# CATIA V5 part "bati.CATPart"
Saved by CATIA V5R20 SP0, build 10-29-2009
Part number: bati
Bounding box of the stored display mesh (mm): x -76 to 40, y -41 to 202.5, z -35 to 30
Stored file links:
  F:\Catia_finish\bati.CATPart
  F:\CATIA\Tige.CATPart
  F:\Catia_finish\ASS_compresseur.CATProduct
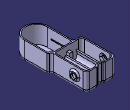
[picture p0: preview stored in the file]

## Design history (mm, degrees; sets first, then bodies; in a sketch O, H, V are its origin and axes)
Parameters
  LENGTH = 20 mm
  LENGTH = 15 mm
  LENGTH = 35 mm
External parameters (linked from other documents)
  External.rayon_piston = 20 mm
  External.excentricite_vilebrequin = 6 mm
  External.longueur_bielle = 35 mm
Set1
  Plane1: linked copy from another document
  Line1: linked copy from another document
  Point1: linked copy from another document
  Line2: linked copy from another document
  Sketch1 on face of Pad2 from Sketch3.L23, origin (-38, 0, 0), H (0, 1, 0), V (0, 0, 1)
    line L1 (59, -2) -> (14, -2)
    line L2 (14, -2) -> (14, 2)
    line L3 (14, 2) -> (59, 2)
    line L4 (59, 2) -> (59, -2)
    reference projected point E1 (55, 0) from Point1
    reference projected line E2 (55, 0) -> (10, 0) from Line2
    length L3 = 45
    distance L4 E1 = 4
    length L2 = 4
    distance L3 E2 = 2
    horizontal: L1 H, L3 H
    vertical: L2 V, L4 V
  Point2: linked copy from another document
  Line3: linked copy from another document
Body1 (main body)
  Sketch2 on xy-plane, origin (0, 0, 0), H (1, 0, 0), V (0, 1, 0)
    point P1 (40, 0)
    line L1 (40, 0) -> (40, 81)
    line L2 (40, 81) -> (30, 81)
    line L3 (30, 81) -> (30, 202.5)
    line L4 (30, 202.5) -> (-10, 202.5)
    line L5 (-10, 202.5) -> (-10, 197.5)
    line L6 (-10, 197.5) -> (-30, 197.5)
    line L7 (-30, 197.5) -> (-30, 202.5)
    point P8 (-30, 202.5)
    line L8 (-30, 202.5) -> (-70, 202.5)
    line L9 (-70, 202.5) -> (-70, 85)
    line L10 (-70, 85) -> (-42, 85)
    line L11 (-42, 85) -> (-42, 0)
    construction line L12 (40, 0) -> (98, 0)
    construction line L13 (-42, 0) -> (-95, 0)
    reference projected line E1 (-20, 120) -> (-20, 20)
    arc A1 centre (-1, 0) radius 41 from (-42, 0) to (40, 0) ccw
    circle A2 centre (0, 0) radius 10
    point P16 (0, 0)
    reference projected point E2 (0, 0)
    axis line L14 (25, 81) -> (-29, 81)
    point P17 (25, 81)
    length L1 = 81 {= External.excentricite_vilebrequin +External.longueur_bielle +40mm}
    distance L9 E1 = 50 {= Sketch2.length(L8) +10mm}
    length L8 = 40 {= LENGTH +20mm}
    length L4 = 40 {= LENGTH +20mm}
    length L6 = 20
    length L3 = 121.5 {= Sketch2.length(L1) *1.5}
    distance L6 L4 = 5
    length L10 = 28
    length L2 = 10
    radius A2 = 10
    coincidence: P1 H, P8 L4, L13 L12, E2 P16, P17 L2
    vertical: L1 V, L3 V, L5 V, L7 V, L9 V, L11 V
    horizontal: L2 H, L4 H, L6 H, L8 H, L10 H, L12 H, L13 H, L14 H
    tangency: A1 L1
  Pad1: profile Sketch2, direction (0, 0, 1), length -30 {= -External.rayon_piston -10mm}, opposite side length 35 {= External.rayon_piston+15mm}
  Sketch3 on end face of Pad1, origin (0, 0, -30), H (1, 0, 0), V (0, 1, 0)
    line L1 (-66, 198.5) -> (-66, 89)
    line L2 (-66, 198.5) -> (-34, 198.5)
    line L3 (-34, 198.5) -> (-34, 193.5)
    line L4 (-34, 193.5) -> (-6, 193.5)
    line L5 (-6, 193.5) -> (-6, 198.5)
    point P7 (-6, 198.5)
    line L6 (-6, 198.5) -> (26, 198.5)
    line L7 (26, 77) -> (36, 77)
    line L8 (36, 77) -> (36, 0)
    point P11 (36, 0)
    reference projected line E1 (-70, 170) -> (-70, 85) from edge [face of Pad1 from Sketch2.L9 | end face of Pad1]
    reference projected line E2 (-30, 202.5) -> (-70, 202.5) from edge [face of Pad1 from Sketch2.L8 | end face of Pad1]
    reference projected line E3 (40, 81) -> (30, 81) from edge [face of Pad1 from Sketch2.L2 | end face of Pad1]
    reference projected line E4 (-30, 165) -> (-30, 170) from edge [face of Pad1 from Sketch2.L7 | end face of Pad1]
    reference projected line E5 (-10, 197.5) -> (-30, 197.5) from edge [face of Pad1 from Sketch2.L6 | end face of Pad1]
    reference projected line E6 (-10, 170) -> (-10, 165) from edge [face of Pad1 from Sketch2.L5 | end face of Pad1]
    construction line L9 (-38, 0) -> (107, 0)
    reference projected point E7 (40, 0) from vertex [face of Pad1 from Sketch2.A1 | end face of Pad1 | face of Pad1 from Sketch2.L1]
    reference projected line E8 (40, 0) -> (40, 85) from edge [face of Pad1 from Sketch2.L1 | end face of Pad1]
    arc A1 centre (-1, 0) radius 37 from (36, 0) to (-38, 0) cw
    point P14 (40, 0)
    line L10 (40, 0) -> (40, 81)
    line L11 (40, 81) -> (30, 81)
    line L12 (30, 81) -> (30, 202.5)
    line L13 (-70, 202.5) -> (-70, 85)
    line L14 (-70, 85) -> (-42, 85)
    line L15 (-42, 85) -> (-42, 0)
    point P21 (-42, 0)
    reference projected line E9 (40, 0) -> (40, 85) from edge [face of Pad1 from Sketch2.L1 | end face of Pad1]
    reference projected line E10 (30, 85) -> (30, 170) from edge [face of Pad1 from Sketch2.L3 | end face of Pad1]
    reference projected line E11 (-70, 170) -> (-70, 85) from edge [face of Pad1 from Sketch2.L9 | end face of Pad1]
    reference projected line E12 (-70, 85) -> (-42, 85) from edge [face of Pad1 from Sketch2.L10 | end face of Pad1]
    reference projected line E13 (-42, 85) -> (-42, 0) from edge [face of Pad1 from Sketch2.L11 | end face of Pad1]
    reference projected line E14 (40, 81) -> (30, 81) from edge [face of Pad1 from Sketch2.L2 | end face of Pad1]
    line L16 (30, 202.5) -> (-10, 202.5)
    line L17 (-10, 202.5) -> (-10, 197.5)
    line L18 (-10, 197.5) -> (-30, 197.5)
    line L19 (-30, 197.5) -> (-30, 202.5)
    point P25 (-30, 202.5)
    line L20 (-30, 202.5) -> (-70, 202.5)
    reference projected line E15 (30, 202.5) -> (-10, 202.5) from edge [face of Pad1 from Sketch2.L4 | end face of Pad1]
    reference projected line E16 (-30, 165) -> (-30, 170) from edge [face of Pad1 from Sketch2.L7 | end face of Pad1]
    reference projected line E17 (-10, 170) -> (-10, 165) from edge [start face of Pad1 | face of Pad1 from Sketch2.L5]
    reference projected line E18 (-10, 197.5) -> (-30, 197.5) from edge [face of Pad1 from Sketch2.L6 | end face of Pad1]
    arc A2 centre (-1, 0) radius 41 from (-42, 0) to (40, 0) ccw
    line L21 (26, 198.5) -> (26, 89)
    point P28 (26, 85)
    line L22 (26, 85) -> (26, 77)
    point P29 (-38, 85)
    line L23 (-38, 85) -> (-38, 0)
    axis line L24 (26, 85) -> (68, 85)
    line L25 (26, 85) -> (-38, 85)
    line L26 (26, 89) -> (-66, 89)
    distance L1 E1 = 4
    distance L2 E2 = 4
    distance E3 L7 = 4
    distance L3 E4 = 4
    distance L4 E5 = 4
    distance L5 E6 = 4
    distance L8 E8 = 4
    vertical: L1 V, L3 V, L5 V, L8 V, L10 V, L12 V, L13 V, L15 V, L17 V, L19 V, L21 V, L22 V
    horizontal: L2 H, L4 H, L6 H, L7 H, L9 H, L11 H, L14 H, L16 H, L18 H, L20 H, L24 H, L25 H, L26 H
    coincidence: P7 L2, P11 L9, L9 E7, P14 H, E9 L10, E10 L12, L13 E11, L14 E12, L15 E13, L11 E14, P25 L16, L16 E15, L19 E16, L17 E17, E18 L18, P21 L9, P28 L21, L24 P29, L14 P29
    tangency: A2 L15, L23 A1
  Pad2: profile Sketch3, direction (0, 0, 1), length 60 {= External.rayon_piston *2+20mm}
  Sketch4 on face of Pad2 from Sketch3.L25, origin (0, 85, 0), H (1, 0, 0), V (0, 0, 1)
    circle A1 centre (-20, 0) radius 2.5
    point P1 (-20, 0)
    reference projected point E1 (-20, 0) from Line1
    radius A1 = 2.5
    coincidence: P1 E1
  Pocket1: profile Sketch4, direction (0, 1, 0), length 38
  Sketch5 on face of Pad2 from Sketch3.L26, origin (0, 89, 0), H (-1, 0, 0), V (0, 0, 1)
    line L1 (25, -23.8118) -> (25, -30)
    line L2 (25, -30) -> (15, -30)
    line L3 (15, -30) -> (15, -23.8118)
    point P4 (25, 23.8118)
    line L4 (25, 23.8118) -> (25, 30)
    line L5 (25, 30) -> (15, 30)
    line L6 (15, 30) -> (15, 23.8118)
    point P7 (15, 23.8118)
    reference projected line E1 (66, 30) -> (-26, 30) from edge [end face of Pad2 | face of Pad2 from Sketch3.L26]
    reference projected line E2 (66, -30) -> (-26, -30) from edge [face of Pad2 from Sketch3.L26 | end face of Pad1]
    circle A1 centre (20, 0) radius 20
    point P8 (20, 0)
    reference projected point E3 (20, 0) from Line1
    reference projected point E4 (20, 0) from Line1
    arc A2 centre (20, 0) radius 24.3311 from (25, -23.8118) to (25, 23.8118) ccw
    arc A3 centre (20, 0) radius 24.3311 from (15, 23.8118) to (15, -23.8118) ccw
    radius A1 = 20 {= External.rayon_piston}
    distance L3 L1 = 10
    distance L6 E4 = 5
    vertical: L1 V, L3 V, L4 V, L6 V
    horizontal: L2 H, L5 H
    coincidence: P4 L1, L5 E1, L2 E2, L6 L3, P8 E3, P7 A2, A2 A3
  Pad3: profile Sketch5, direction (0, 1, 0), length 99.5 {= Sketch2.length(L3) -22mm}, opposite side length -11
  Fillet1: radius 8, on edge [face of Pad2 | face of Pad2]
  Fillet2: radius 5, on edge [face of Pad2 | face of Pad2]
  Fillet3: radius 7, on edge [face of Pad2 | face of Pad2]
  Sketch6 on face of Pad2 from Sketch3.L26, origin (0, 89, 0), H (-1, 0, 0), V (0, 0, 1)
    line L1 (25, 30) -> (15, 30)
    line L2 (15, 30) -> (15, -30)
    line L3 (15, -30) -> (25, -30)
    line L4 (25, -30) -> (25, 30)
    reference projected line E1 (66, -30) -> (-26, -30) from edge [face of Pad2 from Sketch3.L26 | end face of Pad1]
    reference projected line E2 (66, 30) -> (-26, 30) from edge [end face of Pad2 | face of Pad2 from Sketch3.L26]
    reference projected line E3 (15, 30) -> (15, 23.8118) from edge [start face of Pad3 | face of Pad3 from Sketch5.L6]
    reference projected line E4 (25, 23.8118) -> (25, 30) from edge [start face of Pad3 | face of Pad3 from Sketch5.L4]
    horizontal: L1 H, L3 H
    vertical: L2 V, L4 V
    coincidence: L3 E1, L1 E2, E3 L2, L4 E4
  Pad4: profile Sketch6, direction (0, 1, 0), length 11
  Sketch7 on face of Pad2 from Sketch3.L4, origin (0, 193.5, 0), H (1, 0, 0), V (0, 0, 1)
    line L1 (-15, 30) -> (-25, 30)
    line L2 (-25, 30) -> (-25, -30)
    line L3 (-25, -30) -> (-15, -30)
    line L4 (-15, -30) -> (-15, 30)
    reference projected line E1 (-6, -30) -> (-34, -30) from edge [face of Pad2 from Sketch3.L4 | end face of Pad1]
    reference projected line E2 (-6, 30) -> (-34, 30) from edge [end face of Pad2 | face of Pad2 from Sketch3.L4]
    reference projected line E3 (-15, -30) -> (-15, -23.8118) from edge [face of Pad4 | end face of Pad3]
    reference projected line E5 (-25, 23.8118) -> (-25, 30) from edge [face of Pad4 | end face of Pad3]
    horizontal: L1 H, L3 H
    vertical: L2 V, L4 V
    coincidence: L3 E1, L1 E2, L4 E3, E5 L2
  Pad5: profile Sketch7, direction (0, -1, 0), length 11
  Fillet4: radius 4, on edge [face of Pad2 from Sketch3.L5 | face of Pad2 from Sketch3.L4]; edge [face of Pad2 from Sketch3.L4 | face of Pad2 from Sketch3.L3]
  Fillet5: radius 4, on edge [face of Pad2 | face of Pad2]
  Fillet6: radius 4, on edge [face of Pad2 | face of Pad2]
  Fillet7: radius 4, on edge [face of Pad2 | face of Pad2]
  Fillet8: radius 4, on edge [face of Pad2 | face of Pad2]
  Fillet9: radius 11, on edge [face of Pad2 | face of Pad2] (x3); edge [face of Pad2 from Sketch3.L2 | face of Pad2 from Sketch3.L1]; edge [face of Pad2 from Sketch3.L1 | face of Pad2 from Sketch3.L26]; edge [face of Pad2 from Sketch3.L21 | face of Pad2 from Sketch3.L6]
  Fillet10: radius 11, on edge [start face of Pad1 | face of Pad2] (x9); edge [face of Fillet3 | start face of Pad1]; edge [start face of Pad1 | face of Fillet9] (x3); edge [face of Fillet6 | start face of Pad1]; edge [face of Fillet5 | start face of Pad1]; edge [face of Fillet1 | start face of Pad1]; edge [start face of Pad1 | face of Fillet2]
  Fillet11: radius 4, on edge [face of Pad2 from Sketch3.L25 | face of Pad2 from Sketch3.L23]
  Sketch8 on face of Pad2, origin (30, 0, 0), H (0, 1, 0), V (0, 0, 1)
    circle A1 centre (162.5, 3) radius 12.5
    point P1 (162.5, 3)
    reference projected line E1 (202.5, -35) -> (202.5, 30) from edge [face of Pad2 | face of Fillet9]
    reference projected line E2 (93, -35) -> (159, -35) from edge [start face of Pad1 | face of Fillet10]
    distance E1 P1 = 40
    distance E2 P1 = 38
    radius A1 = 12.5
  Pad6: profile Sketch8, direction (1, 0, 0), length 6
  Sketch9 on end face of Pad6, origin (36, 0, 0), H (0, 1, 0), V (0, 0, 1)
    circle A1 centre (162.5, 3) radius 9
    reference projected circle E1 centre (162.5, 3) radius 12.5 from edge [face of Pad6 from Sketch8.A1 | end face of Pad6]
    radius A1 = 9
    concentricity: A1 E1
  Pocket2: profile Sketch9, direction (-1, 0, 0), length 14
  Sketch10 on face of Pad2, origin (-70, 0, 0), H (0, -1, 0), V (0, 0, 1)
    circle A1 centre (-164.5, 5) radius 12.5
    point P1 (-164.5, 5)
    reference projected line E1 (-202.5, -35) -> (-202.5, 30) from edge [face of Fillet9 | face of Pad2]
    reference projected line E2 (-159, -35) -> (-96, -35) from edge [start face of Pad1 | face of Fillet10]
    radius A1 = 12.5
    distance P1 E1 = 38
    distance E2 P1 = 40
  Pad7: profile Sketch10, direction (-1, 0, 0), length 6
  Sketch11 on end face of Pad7, origin (-76, 0, 0), H (0, -1, 0), V (0, 0, 1)
    circle A1 centre (-164.5, 5) radius 9
    reference projected circle E1 centre (-164.5, 5) radius 12.5 from edge [face of Pad7 from Sketch10.A1 | end face of Pad7]
    radius A1 = 9
    concentricity: A1 E1
  Pocket3: profile Sketch11, direction (1, 0, 0), length 14
  Fillet12: radius 5, on edge [face of Pad2 | face of Pad7 from Sketch10.A1]; edge [face of Pad2 | face of Pad6 from Sketch8.A1]
  Fillet13: radius 5, on edge [face of Pad2 from Sketch3.L21 | face of Pocket2 from Sketch9.A1]; edge [face of Pocket3 from Sketch11.A1 | face of Pad2 from Sketch3.L1]
  Pocket4: profile Sketch1, direction (-1, 0, 0), length 1
  Sketch12 on face of Pad2 from Sketch3.L8, origin (36, 0, 0), H (0, -1, 0), V (0, 0, 1)
    line L1 (-10, 8) -> (-60, 8)
    line L2 (-60, 8) -> (-60, -8)
    line L3 (-60, -8) -> (-10, -8)
    line L4 (-10, -8) -> (-10, 8)
    reference projected line E1 (-70, 0) -> (-15, 0) from Line3
    reference projected point E2 (-70, 0) from Point2
    length L1 = 50
    length L4 = 16
    distance E1 L1 = 8
    distance L4 E2 = 60
    horizontal: L1 H, L3 H
    vertical: L2 V, L4 V
  Pocket5: profile Sketch12, direction (1, 0, 0), length 1.8
  Sketch13 on face of Pad5, origin (0, 0, 30), H (1, 0, 0), V (0, 1, 0)
    line L1 (-55, 193.5) -> (10, 193.5)
    line L2 (10, 193.5) -> (10, 89)
    line L3 (10, 89) -> (-55, 89)
    line L4 (-55, 89) -> (-55, 193.5)
    point P4 (-55, 89)
    reference projected line E1 (-66, 89) -> (26, 89) from edge [face of Pad5 | face of Pad2 from Sketch3.L26]
    reference projected line E2 (-34, 193.5) -> (-25, 193.5) from edge [face of Pad5 | face of Pad2 from Sketch3.L4]
    reference projected point E4 (-55, 89) from vertex [face of Fillet9 | face of Pad2 from Sketch3.L26 | face of Pad5]
    horizontal: L1 H, L3 H
    vertical: L2 V, L4 V
    coincidence: L3 E1, L1 E2, P4 E4
  Pocket6: profile Sketch13, direction (0, 0, -1), length 16.8
  Fillet14: radius 5, on edge [face of Pocket6 | face of Pad2 from Sketch3.L21]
